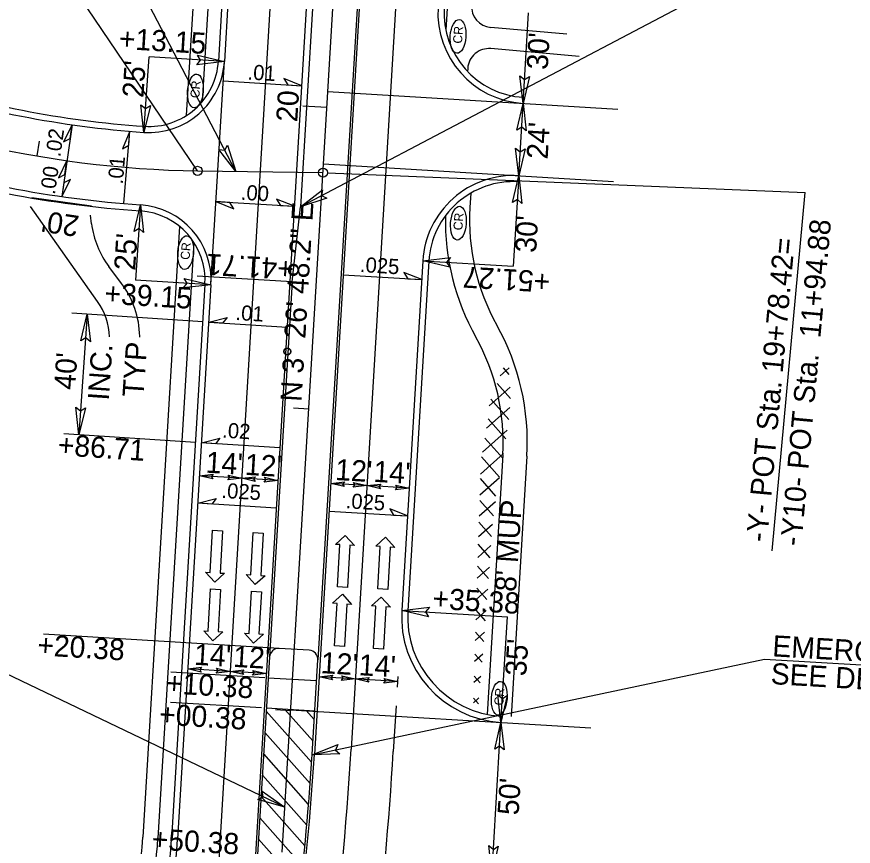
# Model space of a CAD drawing. Extents: x 2010838 to 2015151, y 441905 to 447792.
# Drawn here: x 2011964.2 to 2012241, y 445190.9 to 445465.4 of the extents above; entities that cross this region are included whole.
import ezdxf

# ---------------------------------------------------------------- set-up
doc = ezdxf.new("R2010")
doc.units = 0
for name, color, linetype in [('1-BUFFER', 7, 'Continuous'), ('A-Wall-Abov', 7, 'Continuous'), ('A-Wall-Blow', 7, 'Continuous'), ('A-Wall-Comp', 7, 'Continuous'), ('B-Border', 7, 'Continuous'), ('C - EC', 7, 'Continuous'), ('C-Building', 7, 'Continuous'), ('C-CURB STOPS', 7, 'Continuous'), ('C-EOP 1', 7, 'Continuous'), ('C-Grave Plots', 7, 'Continuous'), ('C-Profile', 7, 'Continuous'), ('C-SHBD-TEXT', 7, 'Continuous'), ('CLRD', 7, 'Continuous'), ('Cont-2-Lidar', 7, 'Continuous'), ('DEED', 7, 'Continuous'), ('Default_10ft_LIDAR_Contou', 7, 'Continuous'), ('Default_2FT_LIDAR_Contour', 7, 'Continuous'), ('HATCH', 7, 'Continuous'), ('s-Existing Major', 7, 'Continuous'), ('S-Existing Minor', 7, 'Continuous'), ('S-overhead electric', 7, 'Continuous'), ('TEXT-LG', 7, 'Continuous'), ('TEXT-MED', 7, 'Continuous'), ('X2', 7, 'Continuous'), ('X4', 7, 'Continuous')]:
    doc.layers.add(name, color=color, linetype=linetype)

msp = doc.modelspace()

# ---------------------------------------------------------------- linework, layer by layer
at = {"layer": '1-BUFFER'}
for p, q in [((2012114.44, 445407.05), (2012114.15, 445402.26)), ((2012125.01, 445320.46), (2012119.83, 445234.55)), ((2012132.99, 445319.98), (2012127.81, 445233.89)), ((2012063.39, 445245.62), (2012047.42, 445246.58)), ((2012062.79, 445235.64), (2012046.82, 445236.6)), ((2012061.77, 445218.7), (2012046.76, 445235.63)), ((2012062.2, 445225.76), (2012052.91, 445236.23)), ((2012062.62, 445232.82), (2012059.97, 445235.81)), ((2012061.29, 445211.7), (2012046.34, 445228.57)), ((2012060.76, 445204.77), (2012045.91, 445221.52)), ((2012060.17, 445197.89), (2012045.49, 445214.46)), ((2012059.53, 445191.08), (2012045.06, 445207.4)), ((2012057.47, 445185.87), (2012044.64, 445200.34)), ((2012050.41, 445186.29), (2012044.21, 445193.28))]:
    msp.add_line(p, q, dxfattribs=at)
for centre, radius, start, end in [((2012185.03, 445398), 71, 176.5533, 209.2367), ((2012185.03, 445398), 79, 178.8752, 209.2367), ((2012054.13, 445324.73), 79, 356.5533, 29.2367), ((2012054.13, 445324.73), 71, 356.5533, 29.2367)]:
    msp.add_arc(centre, radius, start, end, dxfattribs=at)
at = {"layer": 'A-Wall-Abov'}
for p, q in [((2012028.19, 445281.52), (2012028.98, 445295.5)), ((2012028.98, 445295.5), (2012032.28, 445295.31)), ((2012032.28, 445295.31), (2012031.48, 445281.33)), ((2012041.61, 445280.73), (2012042.41, 445294.7)), ((2012042.41, 445294.7), (2012045.71, 445294.52)), ((2012045.71, 445294.52), (2012044.91, 445280.54)), ((2012069.64, 445290.82), (2012072.92, 445293.79)), ((2012072.92, 445293.79), (2012075.93, 445290.46)), ((2012083, 445290.18), (2012086.27, 445293.15)), ((2012086.27, 445293.15), (2012089.28, 445289.82)), ((2012071.14, 445290.74), (2012069.64, 445290.82)), ((2012070.34, 445276.76), (2012071.14, 445290.74)), ((2012074.44, 445290.55), (2012073.64, 445276.57)), ((2012075.93, 445290.46), (2012074.44, 445290.55)), ((2012084.49, 445290.09), (2012083, 445290.18)), ((2012083.7, 445276.12), (2012084.49, 445290.09)), ((2012087.79, 445289.91), (2012086.99, 445275.93)), ((2012089.28, 445289.82), (2012087.79, 445289.91)), ((2012029.71, 445278.28), (2012026.69, 445281.6)), ((2012026.69, 445281.6), (2012028.19, 445281.52)), ((2012032.98, 445281.25), (2012029.71, 445278.28)), ((2012031.48, 445281.33), (2012032.98, 445281.25)), ((2012043.13, 445277.49), (2012040.12, 445280.81)), ((2012040.12, 445280.81), (2012041.61, 445280.73)), ((2012046.41, 445280.45), (2012043.13, 445277.49)), ((2012044.91, 445280.54), (2012046.41, 445280.45)), ((2012027.56, 445262.13), (2012028.36, 445276.1)), ((2012028.36, 445276.1), (2012031.65, 445275.92)), ((2012031.65, 445275.92), (2012030.86, 445261.94)), ((2012041.05, 445261.36), (2012041.85, 445275.33)), ((2012041.85, 445275.33), (2012045.14, 445275.15)), ((2012045.14, 445275.15), (2012044.35, 445261.17)), ((2012073.64, 445276.57), (2012070.34, 445276.76)), ((2012086.99, 445275.93), (2012083.7, 445276.12)), ((2012068.67, 445271.32), (2012071.94, 445274.29)), ((2012071.94, 445274.29), (2012074.96, 445270.96)), ((2012081.56, 445270.43), (2012084.83, 445273.4)), ((2012084.83, 445273.4), (2012087.85, 445270.07)), ((2012070.17, 445271.23), (2012068.67, 445271.32)), ((2012069.37, 445257.26), (2012070.17, 445271.23)), ((2012073.46, 445271.04), (2012072.66, 445257.07)), ((2012074.96, 445270.96), (2012073.46, 445271.04)), ((2012083.06, 445270.34), (2012081.56, 445270.43)), ((2012082.26, 445256.37), (2012083.06, 445270.34)), ((2012086.35, 445270.16), (2012085.55, 445256.18)), ((2012087.85, 445270.07), (2012086.35, 445270.16)), ((2012029.08, 445258.88), (2012026.06, 445262.21)), ((2012026.06, 445262.21), (2012027.56, 445262.13)), ((2012032.35, 445261.85), (2012029.08, 445258.88)), ((2012030.86, 445261.94), (2012032.35, 445261.85)), ((2012042.57, 445258.12), (2012039.55, 445261.44)), ((2012039.55, 445261.44), (2012041.05, 445261.36)), ((2012045.84, 445261.08), (2012042.57, 445258.12)), ((2012044.35, 445261.17), (2012045.84, 445261.08)), ((2012072.66, 445257.07), (2012069.37, 445257.26)), ((2012085.55, 445256.18), (2012082.26, 445256.37))]:
    msp.add_line(p, q, dxfattribs=at)
at = {"layer": 'A-Wall-Blow'}
for p, q in [((2012032.52, 445444.16), (2012058.48, 445442.59)), ((2011982.49, 445429.66), (2011979.1, 445405.9)), ((2011999.68, 445403.58), (2012001.66, 445427.5)), ((2012030.12, 445404.23), (2012056.07, 445402.67)), ((2012072.24, 445379.97), (2012098.19, 445378.41)), ((2012027.71, 445364.3), (2012053.67, 445362.74)), ((2012051.26, 445322.81), (2012025.31, 445324.37)), ((2012050.06, 445302.85), (2012024.11, 445304.41)), ((2012067.53, 445301.8), (2012093.48, 445300.23))]:
    msp.add_line(p, q, dxfattribs=at)
at = {"layer": 'A-Wall-Comp'}
for points in [[(2012058.48, 445442.59), (2012052.61, 445444.95), (2012053.86, 445442.87)], [(2011982.49, 445429.66), (2011979.66, 445424), (2011981.84, 445425.08)], [(2012001.66, 445427.5), (2011999.17, 445421.68), (2012001.28, 445422.89)], [(2011980.8, 445417.78), (2011977.97, 445412.12), (2011980.15, 445413.2)], [(2011979.1, 445405.9), (2011981.93, 445411.55), (2011979.76, 445410.48)], [(2012030.12, 445404.23), (2012035.99, 445401.87), (2012034.74, 445403.95)], [(2012056.07, 445402.67), (2012050.2, 445405.02), (2012051.46, 445402.95)], [(2012098.19, 445378.41), (2012092.32, 445380.76), (2012093.57, 445378.68)], [(2012027.71, 445364.3), (2012033.82, 445365.94), (2012032.33, 445364.02)], [(2012025.31, 445324.37), (2012031.42, 445326.01), (2012029.93, 445324.1)], [(2012024.11, 445304.41), (2012030.22, 445306.05), (2012028.72, 445304.13)], [(2012093.48, 445300.23), (2012087.61, 445302.59), (2012088.87, 445300.51)]]:
    msp.add_lwpolyline(points, close=True, dxfattribs=at)
at = {"layer": 'B-Border'}
for p, q in [((2012028.46, 445376.72), (2012032.91, 445450.59)), ((2012089.7, 445237.41), (2012088.79, 445222.25))]:
    msp.add_line(p, q, dxfattribs=at)
msp.add_arc((2011076.45, 445280.41), 1014, 352.74315, 356.71393, dxfattribs=at)
at = {"layer": 'C - EC'}
for p, q in [((2012124.14, 445346.59), (2012127.16, 445349.28)), ((2012127.19, 445347.02), (2012125.21, 445349.25)), ((2012120.52, 445336.69), (2012127.43, 445342.82)), ((2012127.55, 445339.1), (2012123.12, 445344.07)), ((2012127.02, 445332.16), (2012121.04, 445338.89)), ((2012119.65, 445329.23), (2012127.36, 445336.08)), ((2012126.04, 445325.74), (2012120.14, 445332.37)), ((2012118.27, 445321.31), (2012126.47, 445328.6)), ((2012125.03, 445319.35), (2012119.12, 445325.99)), ((2012117.68, 445314.1), (2012125.27, 445320.84)), ((2012123.95, 445313.03), (2012117.97, 445319.76)), ((2012117.45, 445307.2), (2012123.94, 445312.97)), ((2012122.78, 445306.82), (2012117.63, 445312.62)), ((2012117.21, 445300.3), (2012122.56, 445305.05)), ((2012121.94, 445300.24), (2012117.38, 445305.37)), ((2012116.97, 445293.4), (2012121.58, 445297.5)), ((2012121.29, 445293.45), (2012117.13, 445298.12)), ((2012116.73, 445286.5), (2012121.11, 445290.39)), ((2012120.88, 445286.38), (2012116.88, 445290.88)), ((2012120.29, 445279.51), (2012116.63, 445283.63)), ((2012116.51, 445279.61), (2012120.61, 445283.25)), ((2012116.3, 445272.74), (2012120.03, 445276.05)), ((2012119.8, 445272.54), (2012116.41, 445276.36)), ((2012116.1, 445265.87), (2012119.57, 445268.95)), ((2012119.31, 445265.57), (2012116.19, 445269.07)), ((2012115.89, 445259), (2012119.01, 445261.77)), ((2012118.77, 445258.65), (2012115.98, 445261.79)), ((2012115.69, 445252.13), (2012118.42, 445254.55)), ((2012118.16, 445251.8), (2012115.76, 445254.51)), ((2012115.49, 445245.26), (2012117.75, 445247.26)), ((2012117.54, 445244.98), (2012115.54, 445247.22)), ((2012115.28, 445238.39), (2012117.1, 445240.01)), ((2012116.95, 445238.11), (2012115.33, 445239.94))]:
    msp.add_line(p, q, dxfattribs=at)
at = {"layer": 'C-Building'}
for p, q in [((2011970.92, 445419.33), (2011971.77, 445424.26)), ((2012060.8, 445335.56), (2012055.81, 445335.86)), ((2012054.78, 445235.74), (2012049.79, 445236.04))]:
    msp.add_line(p, q, dxfattribs=at)
at = {"layer": 'C-CURB STOPS'}
for p, q in [((2012061, 445255.78), (2012051.02, 445256.38)), ((2012047.84, 445253.57), (2012041.75, 445152.34)), ((2012061.93, 445221.34), (2012063.82, 445252.61))]:
    msp.add_line(p, q, dxfattribs=at)
for centre, radius, start, end in [((2012050.84, 445253.39), 3, 86.5533, 176.5533), ((2012060.82, 445252.79), 3, 356.5533, 86.5533), ((2011264.13, 445269.39), 799.25, 349.26091, 356.55328)]:
    msp.add_arc(centre, radius, start, end, dxfattribs=at)
at = {"layer": 'C-EOP 1'}
msp.add_line((2012066.81, 445435.38), (2012058.82, 445435.86), dxfattribs=at)
at = {"layer": 'C-Profile'}
msp.add_line((2012063.14, 445486.74), (2012058.07, 445402.55), dxfattribs=at)
at = {"layer": 'C-SHBD-TEXT'}
for p, q in [((2012067.13, 445440.64), (2012163.06, 445434.86)), ((2012065.68, 445416.68), (2012161.61, 445410.9)), ((2012054.81, 445236.12), (2012154.18, 445230.13))]:
    msp.add_line(p, q, dxfattribs=at)
at = {"layer": 'CLRD'}
for p, q in [((2012051.97, 445189.02), (2012069.62, 445482)), ((2012024.02, 445414.41), (2012065.51, 445413.83)), ((2012024.02, 445414.41), (2012065.51, 445413.83))]:
    msp.add_line(p, q, dxfattribs=at)
msp.add_arc((2012028.74, 445754.16), 339.78, 243.3399, 269.2048, dxfattribs=at)
msp.add_arc((2012028.74, 445754.16), 339.78, 243.3399, 269.2048, dxfattribs=at)
at = {"layer": 'DEED'}
for p, q in [((2012077.6, 445481.52), (2012063.82, 445252.61)), ((2012055.32, 445377.67), (2012058.07, 445402.55)), ((2012055.32, 445377.67), (2012047.84, 445253.57))]:
    msp.add_line(p, q, dxfattribs=at)
at = {"layer": 'Default_10ft_LIDAR_Contou'}
for p, q in [((2012036.67, 445414.23), (2011970.1, 445542.15)), ((2012024.02, 445414.41), (2011944.05, 445532.71)), ((2012067.01, 445413.77), (2012225.1, 445407.21)), ((2012214.2, 445288.67), (2012225.1, 445407.21)), ((2012052.87, 445203.91), (2011954.92, 445250.82))]:
    msp.add_line(p, q, dxfattribs=at)
for centre in [(2012024.02, 445414.41), (2012065.51, 445413.83)]:
    msp.add_circle(centre, 1.5, dxfattribs=at)
at = {"layer": 'HATCH'}
for p, q in [((2012048.9, 445483.24), (2012030.81, 445182.86)), ((2012090.33, 445480.75), (2012074.81, 445223.09)), ((2012090.28, 445247.14), (2012090.07, 445243.55))]:
    msp.add_line(p, q, dxfattribs=at)
msp.add_arc((2011076.45, 445280.41), 1000, 347.80893, 356.71393, dxfattribs=at)
at = {"layer": 's-Existing Major'}
for points in [[(2012024.02, 445452.68), (2012032.91, 445450.59), (2012023.78, 445449.54), (2012025.03, 445451.06)], [(2012133.85, 445445.63), (2012131.76, 445436.74), (2012130.71, 445445.87), (2012132.23, 445444.63)], [(2012008.41, 445436.02), (2012006.24, 445427.15), (2012005.27, 445436.29), (2012006.78, 445435.03)], [(2012129.67, 445427.85), (2012131.76, 445436.74), (2012132.81, 445427.61), (2012131.28, 445428.86)], [(2012033.89, 445422.93), (2012036.67, 445414.23), (2012031.08, 445421.52), (2012033.03, 445421.24)], [(2012132.4, 445421.68), (2012130.32, 445412.79), (2012129.26, 445421.92), (2012130.79, 445420.67)], [(2012128.23, 445403.9), (2012130.32, 445412.79), (2012131.37, 445403.66), (2012129.84, 445404.9)], [(2012066.76, 445405.36), (2012058.07, 445402.55), (2012065.33, 445408.18), (2012065.06, 445406.22)], [(2012003.03, 445394.29), (2012005.18, 445403.17), (2012006.17, 445394.03), (2012004.65, 445395.28)], [(2012107.46, 445382.56), (2012098.57, 445384.65), (2012107.7, 445385.7), (2012106.45, 445384.17)], [(2012019.57, 445378.81), (2012028.46, 445376.72), (2012019.33, 445375.67), (2012020.58, 445377.2)], [(2011985.42, 445358.11), (2011987.48, 445367.01), (2011988.56, 445357.88), (2011987.03, 445359.12)], [(2011986.94, 445335.97), (2011984.78, 445327.1), (2011983.8, 445336.24), (2011985.32, 445334.98)], [(2012029.1, 445312.48), (2012024.66, 445313.51), (2012029.22, 445314.05), (2012028.6, 445313.28)], [(2012034.19, 445313.73), (2012038.63, 445312.69), (2012034.07, 445312.16), (2012034.69, 445312.92)], [(2012043.08, 445311.65), (2012038.63, 445312.69), (2012043.2, 445313.22), (2012042.57, 445312.46)], [(2012046.16, 445313.02), (2012050.61, 445311.98), (2012046.05, 445311.45), (2012046.67, 445312.22)], [(2012072.53, 445309.92), (2012068.08, 445310.95), (2012072.64, 445311.49), (2012072.02, 445310.72)], [(2012075.61, 445311.29), (2012080.06, 445310.25), (2012075.5, 445309.72), (2012076.12, 445310.48)], [(2012084.51, 445309.21), (2012080.06, 445310.25), (2012084.62, 445310.78), (2012084, 445310.02)], [(2012089.59, 445310.46), (2012094.04, 445309.42), (2012089.47, 445308.89), (2012090.09, 445309.66)], [(2012100.49, 445266.88), (2012091.6, 445268.97), (2012100.73, 445270.02), (2012099.48, 445268.49)], [(2012025.25, 445248.57), (2012020.81, 445249.61), (2012025.37, 445250.14), (2012024.75, 445249.38)], [(2012030.34, 445249.81), (2012034.78, 445248.77), (2012030.22, 445248.24), (2012030.84, 445249)], [(2012039.23, 445247.73), (2012034.78, 445248.77), (2012039.35, 445249.3), (2012038.72, 445248.54)], [(2012042.31, 445249.09), (2012046.76, 445248.05), (2012042.2, 445247.52), (2012042.82, 445248.28)], [(2012068.68, 445245.96), (2012064.23, 445247), (2012068.79, 445247.53), (2012068.17, 445246.76)], [(2012071.76, 445247.31), (2012076.21, 445246.28), (2012071.64, 445245.74), (2012072.26, 445246.51)], [(2012080.65, 445245.24), (2012076.21, 445246.28), (2012080.77, 445246.81), (2012080.15, 445246.04)], [(2012085.73, 445246.47), (2012090.18, 445245.43), (2012085.62, 445244.9), (2012086.24, 445245.67)], [(2012126.52, 445240.82), (2012124.43, 445231.93), (2012123.38, 445241.06), (2012124.91, 445239.81)], [(2012122.34, 445223.03), (2012124.43, 445231.93), (2012125.48, 445222.8), (2012123.96, 445224.04)], [(2012071.05, 445221.48), (2012061.92, 445221.13), (2012070.44, 445224.57), (2012069.65, 445222.77)], [(2012045.42, 445209.19), (2012052.87, 445203.91), (2012044.01, 445206.37), (2012045.74, 445207.32)], [(2012123.51, 445190.91), (2012121.43, 445182.02), (2012120.37, 445191.15), (2012121.9, 445189.9)]]:
    msp.add_lwpolyline(points, close=True, dxfattribs=at)
at = {"layer": 'S-Existing Minor'}
for p, q in [((2012206.76, 445480.76), (2012058.07, 445402.55)), ((2012131.76, 445436.74), (2012133.56, 445466.69)), ((2012006.24, 445427.15), (2012007.96, 445452.09)), ((2012032.91, 445450.59), (2012007.96, 445452.09)), ((2012130.32, 445412.79), (2012131.76, 445436.74)), ((2012130.32, 445412.79), (2012128.51, 445382.84)), ((2012005.18, 445403.17), (2012003.51, 445378.22)), ((2012098.57, 445384.65), (2012128.51, 445382.84)), ((2012028.46, 445376.72), (2012003.51, 445378.22)), ((2012055.32, 445377.67), (2012023.89, 445379.56)), ((2012025.72, 445364.42), (2011982.45, 445367.35)), ((2011987.48, 445367.01), (2011984.78, 445327.1)), ((2012023.31, 445324.5), (2011979.79, 445327.44)), ((2012038.63, 445312.69), (2012024.66, 445313.51)), ((2012050.61, 445311.98), (2012038.63, 445312.69)), ((2012080.06, 445310.25), (2012068.08, 445310.95)), ((2012094.04, 445309.42), (2012080.06, 445310.25)), ((2012091.6, 445268.97), (2012126.54, 445266.86)), ((2012124.43, 445231.93), (2012126.54, 445266.86)), ((2012051.02, 445256.38), (2011973.02, 445261.08)), ((2012061.92, 445221.13), (2012211.68, 445252.84)), ((2012211.68, 445252.84), (2012349.06, 445244.74)), ((2012046.24, 445246.65), (2012015.21, 445248.52)), ((2012034.78, 445248.77), (2012020.81, 445249.61)), ((2012046.76, 445248.05), (2012034.78, 445248.77)), ((2012090.18, 445245.43), (2012064.23, 445247)), ((2012045.2, 445236.7), (2012015.04, 445238.51)), ((2012121.43, 445182.02), (2012124.43, 445231.93))]:
    msp.add_line(p, q, dxfattribs=at)
at = {"layer": 'S-overhead electric'}
for p, q in [((2012034.93, 445484.09), (2012032.91, 445450.59)), ((2012060.88, 445482.52), (2012041.32, 445157.71)), ((2012078.35, 445481.47), (2012062.68, 445221.3)), ((2011990.88, 445371.16), (2011968.72, 445402.56)), ((2011988.91, 445396.92), (2011988.55, 445399.73)), ((2012098.57, 445384.65), (2012091.6, 445268.97)), ((2011998.87, 445377.16), (2011994.68, 445382.74)), ((2012028.46, 445376.72), (2012017.41, 445193.27)), ((2012004.89, 445359.4), (2012004.88, 445359.68))]:
    msp.add_line(p, q, dxfattribs=at)
for centre, radius, start, end in [((2012133.56, 445466.69), 30, 176.5533, 266.5533), ((2012007.96, 445452.09), 25, 266.0644, 356.5533), ((2012028.74, 445754.16), 327.78, 251.7712, 266.0644), ((2012028.74, 445754.16), 351.78, 251.7712, 266.1604), ((2012128.51, 445382.84), 30, 86.5533, 176.5533), ((2012003.51, 445378.22), 25, 356.5533, 86.1604), ((2012018.67, 445400.76), 30, 187.3653, 216.9223), ((2011974.89, 445359.14), 30, 1.0321, 36.9223), ((2011974.89, 445359.14), 20, 1.0321, 36.9223), ((2012126.54, 445266.86), 35, 176.5533, 266.5533), ((2011264.13, 445269.39), 800, 346.38954, 356.55328), ((2011877.67, 445201.69), 140, 309.2044, 356.5533)]:
    msp.add_arc(centre, radius, start, end, dxfattribs=at)
at = {"layer": 'TEXT-LG'}
for p, q in [((2012023.45, 445484.78), (2012020.31, 445432.69)), ((2012028.44, 445484.48), (2012025.6, 445437.34)), ((2012107.3, 445479.73), (2012106.16, 445460.91)), ((2012146.26, 445459.65), (2012121.05, 445461.88)), ((2012150.27, 445452.26), (2012121.02, 445454.85)), ((2012113.42, 445448.3), (2012113.36, 445447.3)), ((2012018.1, 445396), (2012005.93, 445193.96)), ((2012022.8, 445390.75), (2012010.93, 445193.66))]:
    msp.add_line(p, q, dxfattribs=at)
for centre, radius, start, end in [((2012121.67, 445468.85), 7, 176.5533, 264.9431), ((2012120.41, 445447.88), 7, 84.9431, 176.5533), ((2011877.67, 445201.69), 128.5, 309.2044, 356.5533), ((2011877.67, 445201.69), 133.5, 319.5013, 356.5533)]:
    msp.add_arc(centre, radius, start, end, dxfattribs=at)
at = {"layer": 'TEXT-MED'}
for p, q in [((2012032.93, 445484.21), (2012030.92, 445450.71)), ((2012100.56, 445384.53), (2012093.6, 445268.85)), ((2012026.47, 445376.84), (2012015.42, 445193.39))]:
    msp.add_line(p, q, dxfattribs=at)
for centre, radius, start, end in [((2012133.56, 445466.69), 28, 176.5533, 266.5533), ((2012007.96, 445452.09), 23, 266.0644, 356.5533), ((2012028.74, 445754.16), 325.78, 251.7712, 266.0644), ((2012028.74, 445754.16), 353.78, 251.7712, 266.1604), ((2012128.51, 445382.84), 28, 86.5533, 176.5533), ((2012003.51, 445378.22), 23, 356.5533, 86.1604), ((2012126.54, 445266.86), 33, 176.5533, 266.5533), ((2011877.67, 445201.69), 138, 309.2044, 356.5533)]:
    msp.add_arc(centre, radius, start, end, dxfattribs=at)
at = {"layer": 'X2'}
msp.add_line((2011988.94, 445402.72), (2011969.14, 445405.53), dxfattribs=at)
at = {"layer": 'X4'}
for centre, major_axis in [((2012110.22, 445458.89), (0.42, 5.59)), ((2012023.31, 445440.84), (0.45, 5.59)), ((2012110.34, 445397.11), (0.42, 5.59)), ((2012020.08, 445387.35), (0.45, 5.59)), ((2012123.86, 445239.89), (0.42, 5.59))]:
    msp.add_ellipse(centre, major_axis=major_axis, ratio=0.462467, dxfattribs=at)

# ---------------------------------------------------------------- texts
at = {"layer": 'A-Wall-Blow'}
for s, rotation, p in [('.01', 356.5533, (2012040.47, 445444.66)), ('.02', 81.8889, (2011978.6, 445418.82)), ('.01', 85.2614, (2011999.29, 445409.83)), ('.00', 81.8889, (2011976.8, 445406.39)), ('.00', 356.5533, (2012038.23, 445404.87)), ('.025', 356.5533, (2012077.65, 445380.95)), ('.01', 356.5533, (2012036.48, 445365.07)), ('.02', 356.5533, (2012032.08, 445326.15)), ('.025', 356.5533, (2012031.83, 445306.22)), ('.025', 356.5533, (2012072.94, 445302.78))]:
    msp.add_text(s, height=5, rotation=rotation, dxfattribs=at).set_placement(p)
at = {"layer": 'C-Grave Plots'}
for s, rotation, p in [('+13.15', 356.5533, (2011997.84, 445454.8)), ("30'", 86.5533, (2012139.88, 445447.72)), ("25'", 86.0644, (2012006.08, 445438.43)), ("24'", 86.5533, (2012139.86, 445418.11)), ("20'", 171.3004, (2011985.17, 445399.43)), ("30'", 86.5533, (2012136.04, 445387.18)), ("25'", 86.1604, (2012003.35, 445381.28)), ('+41.71', 176.5533, (2012056.03, 445385.26)), ('+51.27', 176.5533, (2012140.91, 445381.06)), ('+39.15', 356.5533, (2011993.09, 445370.49)), ('INC. ', 86.0381, (2011994.64, 445338.29)), ('TYP', 86.0381, (2012006.12, 445339.4)), ("40'", 86.0381, (2011983.48, 445341.81)), ('+86.71', 356.128, (2011977.62, 445320.37)), ("14'", 356.6264, (2012026.58, 445314.56)), ("12'", 356.6264, (2012039.52, 445313.84)), ("12'", 356.6264, (2012069.44, 445312.13)), ("14'", 356.6264, (2012082.08, 445311.53)), ("8' MUP", 86.1976, (2012129.39, 445274.98)), ('+35.38', 356.5533, (2012101.63, 445269.54)), ("35'", 86.3252, (2012132.75, 445247.1)), ("14'", 356.6264, (2012022.74, 445251)), ("12'", 356.6264, (2012035.68, 445250.3)), ("12'", 356.6264, (2012064.63, 445248.23)), ("14'", 356.6264, (2012077.22, 445247.54)), ("50'", 86.3252, (2012130.24, 445201.06))]:
    msp.add_text(s, height=7, rotation=rotation, dxfattribs=at).set_placement(p)
at = {"layer": 'Cont-2-Lidar'}
msp.add_text('N 3%%d 26\' 48.2" E', height=7, rotation=86.5533, dxfattribs=at).set_placement((2012058.42, 445337.89))
at = {"layer": 'Default_10ft_LIDAR_Contou'}
for s, p in [('-Y10- POT Sta.  11+94.88', (2012223.77, 445290.04)), ('-Y- POT Sta. 19+78.42=', (2012212.48, 445291.41))]:
    msp.add_text(s, height=7, rotation=84.7467, dxfattribs=at).set_placement(p)
at = {"layer": 'Default_2FT_LIDAR_Contour'}
msp.add_text('20', height=7, rotation=86.5533, dxfattribs=at).set_placement((2012057.01, 445430.44))
at = {"layer": 'S-Existing Minor'}
for s, rotation, p in [('+20.38', 356.5533, (2011970.86, 445254.13)), ('EMERGENCY VEHICLE ACCESS', 356.6264, (2012214.1, 445253.78)), ('SEE DETAIL SHEET 2C-10', 356.6264, (2012213.56, 445244.62)), ('+10.38', 356.5533, (2012013.45, 445241.57)), ('+00.38', 356.5533, (2012011.17, 445231.22)), ('+50.38', 356.5533, (2012008.73, 445189.91))]:
    msp.add_text(s, height=7, rotation=rotation, dxfattribs=at).set_placement(p)
at = {"layer": 'X4'}
for rotation, p in [(85.6623, (2012111.51, 445456.42)), (85.3788, (2012024.59, 445438.37)), (85.6623, (2012111.63, 445394.65)), (85.3788, (2012021.36, 445384.88)), (85.6623, (2012125.16, 445237.42))]:
    msp.add_text('CR', height=3, rotation=rotation, dxfattribs=at).set_placement(p)

doc.saveas('drawing.dxf')
